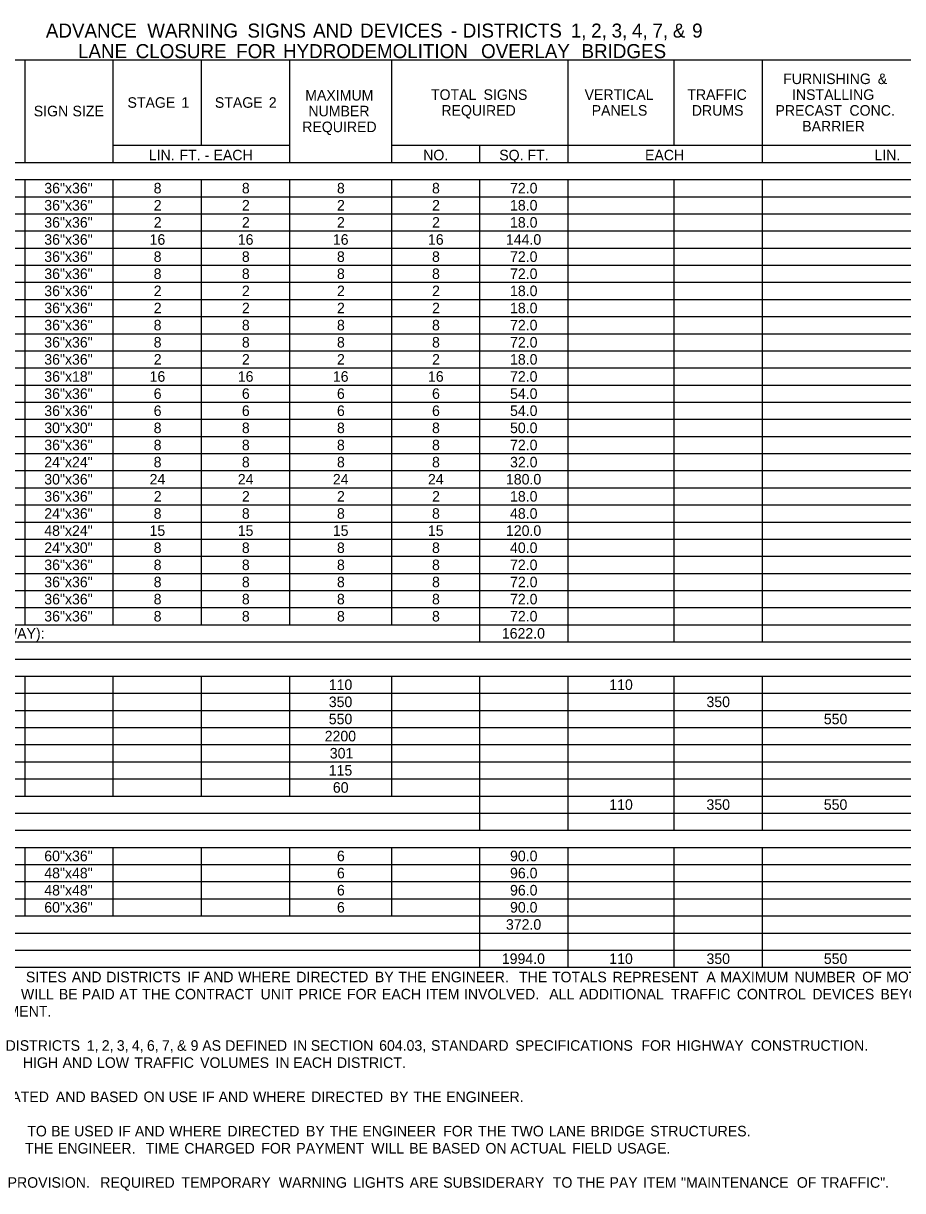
# Model space of a CAD drawing. Extents: x 544255 to 1930787, y -1947044 to 596640.
# Drawn here: x 548600 to 549101, y -1946880 to -1946216 of the extents above; entities that cross this region are included whole.
import ezdxf

# ---------------------------------------------------------------- set-up
doc = ezdxf.new("R2010")
doc.units = 0
doc.layers.add('Default', color=7, linetype='Continuous')

msp = doc.modelspace()

# ---------------------------------------------------------------- linework, layer by layer
at = {"layer": 'Default'}
for p, q in [((548283.35, -1946236.45), (549393.87, -1946236.45)), ((548601.2, -1946294.95), (548601.2, -1946236.45)), ((548651.41, -1946294.95), (548651.41, -1946236.45)), ((548701.62, -1946285.2), (548701.62, -1946236.45)), ((548751.84, -1946294.95), (548751.84, -1946236.45)), ((548809.85, -1946294.95), (548809.85, -1946236.45)), ((548910.27, -1946294.95), (548910.27, -1946236.45)), ((548970.72, -1946285.2), (548970.72, -1946236.45)), ((549020.94, -1946294.95), (549020.94, -1946236.45)), ((548651.41, -1946285.2), (548751.84, -1946285.2)), ((548751.84, -1946294.95), (548751.84, -1946285.2)), ((548809.85, -1946285.2), (549393.87, -1946285.2)), ((548860.06, -1946294.95), (548860.06, -1946285.2)), ((549020.94, -1946294.95), (549020.94, -1946285.2)), ((548283.35, -1946294.95), (549393.87, -1946294.95)), ((548751.84, -1946294.95), (549393.87, -1946294.95)), ((548283.35, -1946304.7), (549393.87, -1946304.7)), ((548601.2, -1946558.2), (548601.2, -1946304.7)), ((548601.2, -1946558.2), (548601.2, -1946304.7)), ((548651.41, -1946558.2), (548651.41, -1946304.7)), ((548651.41, -1946558.2), (548651.41, -1946304.7)), ((548701.62, -1946558.2), (548701.62, -1946304.7)), ((548701.62, -1946558.2), (548701.62, -1946304.7)), ((548751.84, -1946558.2), (548751.84, -1946304.7)), ((548751.84, -1946558.2), (548751.84, -1946304.7)), ((548809.85, -1946558.2), (548809.85, -1946304.7)), ((548860.06, -1946558.2), (548860.06, -1946304.7)), ((548860.06, -1946567.95), (548860.06, -1946304.7)), ((548910.27, -1946548.45), (548910.27, -1946304.7)), ((548910.27, -1946567.95), (548910.27, -1946304.7)), ((548970.72, -1946567.95), (548970.72, -1946304.7)), ((548970.72, -1946567.95), (548970.72, -1946304.7)), ((549020.94, -1946567.95), (549020.94, -1946304.7)), ((549020.94, -1946567.95), (549020.94, -1946304.7)), ((548283.35, -1946314.45), (549393.87, -1946314.45)), ((548283.35, -1946324.2), (549393.87, -1946324.2)), ((548283.35, -1946333.95), (549393.87, -1946333.95)), ((548283.35, -1946343.7), (549393.87, -1946343.7)), ((548283.35, -1946353.45), (549393.87, -1946353.45)), ((548283.35, -1946363.2), (549393.87, -1946363.2)), ((548283.35, -1946372.95), (549393.87, -1946372.95)), ((548283.35, -1946382.7), (549393.87, -1946382.7)), ((548283.35, -1946392.45), (549393.87, -1946392.45)), ((548283.35, -1946402.2), (549393.87, -1946402.2)), ((548283.35, -1946411.95), (549393.87, -1946411.95)), ((548283.35, -1946421.7), (549393.87, -1946421.7)), ((548283.35, -1946431.45), (549393.87, -1946431.45)), ((548283.35, -1946441.2), (549393.87, -1946441.2)), ((548283.35, -1946450.95), (549393.87, -1946450.95)), ((548283.35, -1946460.7), (549393.87, -1946460.7)), ((548283.35, -1946470.45), (549393.87, -1946470.45)), ((548283.35, -1946480.2), (549393.87, -1946480.2)), ((548283.35, -1946489.95), (549393.87, -1946489.95)), ((548283.35, -1946499.7), (549393.87, -1946499.7)), ((548283.35, -1946509.45), (549393.87, -1946509.45)), ((548283.35, -1946519.2), (549393.87, -1946519.2)), ((548283.35, -1946528.95), (549393.87, -1946528.95)), ((548283.35, -1946538.7), (549393.87, -1946538.7)), ((548283.35, -1946548.45), (549393.87, -1946548.45)), ((548283.35, -1946558.2), (549393.87, -1946558.2)), ((548283.35, -1946558.2), (549393.87, -1946558.2)), ((548910.27, -1946567.95), (548910.27, -1946558.2)), ((548283.35, -1946567.95), (549393.87, -1946567.95)), ((548283.35, -1946577.7), (549393.87, -1946577.7)), ((548283.35, -1946577.7), (549393.87, -1946577.7)), ((548283.35, -1946587.45), (549393.87, -1946587.45)), ((548601.2, -1946655.7), (548601.2, -1946587.45)), ((548601.2, -1946655.7), (548601.2, -1946587.45)), ((548651.41, -1946655.7), (548651.41, -1946587.45)), ((548651.41, -1946655.7), (548651.41, -1946587.45)), ((548701.62, -1946655.7), (548701.62, -1946587.45)), ((548701.62, -1946655.7), (548701.62, -1946587.45)), ((548751.84, -1946655.7), (548751.84, -1946587.45)), ((548751.84, -1946655.7), (548751.84, -1946587.45)), ((548809.85, -1946655.7), (548809.85, -1946587.45)), ((548860.06, -1946675.2), (548860.06, -1946587.45)), ((548860.06, -1946675.2), (548860.06, -1946587.45)), ((548910.27, -1946675.2), (548910.27, -1946587.45)), ((548910.27, -1946675.2), (548910.27, -1946587.45)), ((548970.72, -1946675.2), (548970.72, -1946587.45)), ((548970.72, -1946675.2), (548970.72, -1946587.45)), ((549020.94, -1946675.2), (549020.94, -1946587.45)), ((549020.94, -1946675.2), (549020.94, -1946587.45)), ((548283.35, -1946597.2), (549393.87, -1946597.2)), ((548283.35, -1946606.95), (549393.87, -1946606.95)), ((548283.35, -1946616.7), (549393.87, -1946616.7)), ((548601.2, -1946616.7), (548751.84, -1946616.7)), ((548751.84, -1946616.7), (548809.85, -1946616.7)), ((548809.85, -1946616.7), (549020.94, -1946616.7)), ((549020.94, -1946616.7), (549393.87, -1946616.7)), ((548283.35, -1946626.45), (549393.87, -1946626.45)), ((548283.35, -1946636.2), (549393.87, -1946636.2)), ((548283.35, -1946645.95), (549393.87, -1946645.95)), ((548809.85, -1946655.7), (548809.85, -1946645.95)), ((548283.35, -1946655.7), (548809.85, -1946655.7)), ((548283.35, -1946655.7), (549393.87, -1946655.7)), ((548809.85, -1946655.7), (549393.87, -1946655.7)), ((548283.35, -1946665.45), (549393.87, -1946665.45)), ((548283.35, -1946675.2), (549393.87, -1946675.2)), ((548283.35, -1946684.95), (549393.87, -1946684.95)), ((548601.2, -1946723.95), (548601.2, -1946684.95)), ((548651.41, -1946723.95), (548651.41, -1946684.95)), ((548701.62, -1946723.95), (548701.62, -1946684.95)), ((548751.84, -1946723.95), (548751.84, -1946684.95)), ((548809.85, -1946723.95), (548809.85, -1946684.95)), ((548860.06, -1946753.2), (548860.06, -1946684.95)), ((548910.27, -1946753.2), (548910.27, -1946684.95)), ((548910.27, -1946753.2), (548910.27, -1946684.95)), ((548970.72, -1946753.2), (548970.72, -1946684.95)), ((549020.94, -1946753.2), (549020.94, -1946684.95)), ((548283.35, -1946694.7), (549393.87, -1946694.7)), ((548283.35, -1946704.45), (549393.87, -1946704.45)), ((548283.35, -1946714.2), (549393.87, -1946714.2)), ((548283.35, -1946723.95), (549393.87, -1946723.95)), ((548860.06, -1946723.95), (548910.27, -1946723.95)), ((548860.06, -1946753.2), (548860.06, -1946723.95)), ((548910.27, -1946723.95), (549393.87, -1946723.95)), ((548970.72, -1946753.2), (548970.72, -1946723.95)), ((549020.94, -1946753.2), (549020.94, -1946723.95)), ((548283.35, -1946733.7), (549393.87, -1946733.7)), ((548283.35, -1946743.45), (549393.87, -1946743.45)), ((548283.35, -1946753.2), (549393.87, -1946753.2))]:
    msp.add_line(p, q, dxfattribs=at)

# ---------------------------------------------------------------- texts
for s, height, p in [('ADVANCE', 8, (548613, -1946223.88)), (' WARNING', 8, (548667.73, -1946223.88)), (' SIGNS', 8, (548724.79, -1946223.88)), (' AND', 8, (548762.14, -1946223.88)), (' DEVICES', 8, (548788.9, -1946223.88)), (' DISTRICTS', 8, (548847.28, -1946223.88)), (' 1,', 8, (548908.84, -1946223.88)), (' 2,', 8, (548920.45, -1946223.88)), (' 3,', 8, (548932.07, -1946223.88)), (' 4,', 8, (548943.68, -1946223.88)), (' 7,', 8, (548955.3, -1946223.88)), (' &', 8, (548966.92, -1946223.88)), (' 9', 8, (548977.91, -1946223.88)), (' -', 8, (548840.54, -1946223.88)), ('LANE', 8, (548631.29, -1946235.58)), (' CLOSURE', 8, (548661.17, -1946235.58)), (' FOR', 8, (548718.37, -1946235.58)), (' HYDRODEMOLITION', 8, (548745.02, -1946235.58)), (' OVERLAY', 8, (548857.77, -1946235.58)), (' BRIDGES', 8, (548914.93, -1946235.58)), ('FURNISHING', 6, (549032.67, -1946250.33)), (' &', 6, (549084.32, -1946250.33)), ('STAGE', 6, (548659.47, -1946263.83)), (' 1', 6, (548687.94, -1946263.83)), ('STAGE', 6, (548709.21, -1946263.83)), (' 2', 6, (548737.68, -1946263.83)), ('MAXIMUM', 6, (548760.65, -1946259.7)), ('TOTAL', 6, (548832.21, -1946259.33)), (' SIGNS', 6, (548859.9, -1946259.33)), ('VERTICAL', 6, (548919.66, -1946259.33)), ('TRAFFIC', 6, (548978.12, -1946259.33)), ('INSTALLING', 6, (549037.72, -1946259.33)), ('SIGN', 6, (548606.12, -1946268.7)), (' SIZE', 6, (548625.94, -1946268.7)), ('NUMBER', 6, (548762.47, -1946268.7)), ('REQUIRED', 6, (548838.14, -1946268.33)), ('PANELS', 6, (548923.7, -1946268.33)), ('DRUMS', 6, (548980.67, -1946268.33)), ('PRECAST', 6, (549028.29, -1946268.33)), (' CONC.', 6, (549068.18, -1946268.33)), ('REQUIRED', 6, (548758.92, -1946277.7)), ('BARRIER', 6, (549043.54, -1946277.33)), ('LIN.', 6, (548671.59, -1946293.75)), (' FT.', 6, (548686.84, -1946293.75)), (' -', 6, (548701.16, -1946293.75)), (' EACH', 6, (548706.22, -1946293.75)), ('NO.', 6, (548827.79, -1946293.75)), ('SQ.', 6, (548871.07, -1946293.75)), (' FT.', 6, (548884.94, -1946293.75)), ('EACH', 6, (548954.05, -1946293.75)), ('LIN.', 6, (549084.63, -1946293.75)), ('36"x36"', 6, (548612.11, -1946312.58)), ('8', 6, (548674.37, -1946312.58)), ('8', 6, (548724.59, -1946312.58)), ('8', 6, (548778.7, -1946312.58)), ('8', 6, (548832.81, -1946312.58)), ('72.0', 6, (548877.22, -1946312.58)), ('36"x36"', 6, (548612.11, -1946322.33)), ('2', 6, (548674.41, -1946322.33)), ('2', 6, (548724.62, -1946322.33)), ('2', 6, (548778.73, -1946322.33)), ('2', 6, (548832.85, -1946322.33)), ('18.0', 6, (548877.22, -1946322.33)), ('36"x36"', 6, (548612.11, -1946332.08)), ('2', 6, (548674.41, -1946332.08)), ('2', 6, (548724.62, -1946332.08)), ('2', 6, (548778.73, -1946332.08)), ('2', 6, (548832.85, -1946332.08)), ('18.0', 6, (548877.22, -1946332.08)), ('36"x36"', 6, (548612.11, -1946341.83)), ('16', 6, (548672.05, -1946341.83)), ('16', 6, (548722.26, -1946341.83)), ('16', 6, (548776.37, -1946341.83)), ('16', 6, (548830.49, -1946341.83)), ('144.0', 6, (548874.89, -1946341.83)), ('36"x36"', 6, (548612.11, -1946351.58)), ('8', 6, (548674.37, -1946351.58)), ('8', 6, (548724.59, -1946351.58)), ('8', 6, (548778.7, -1946351.58)), ('8', 6, (548832.81, -1946351.58)), ('72.0', 6, (548877.22, -1946351.58)), ('36"x36"', 6, (548612.11, -1946361.33)), ('8', 6, (548674.37, -1946361.33)), ('8', 6, (548724.59, -1946361.33)), ('8', 6, (548778.7, -1946361.33)), ('8', 6, (548832.81, -1946361.33)), ('72.0', 6, (548877.22, -1946361.33)), ('36"x36"', 6, (548612.11, -1946371.08)), ('2', 6, (548674.41, -1946371.08)), ('2', 6, (548724.62, -1946371.08)), ('2', 6, (548778.73, -1946371.08)), ('2', 6, (548832.85, -1946371.08)), ('18.0', 6, (548877.22, -1946371.08)), ('36"x36"', 6, (548612.11, -1946380.83)), ('2', 6, (548674.41, -1946380.83)), ('2', 6, (548724.62, -1946380.83)), ('2', 6, (548778.73, -1946380.83)), ('2', 6, (548832.85, -1946380.83)), ('18.0', 6, (548877.22, -1946380.83)), ('36"x36"', 6, (548612.11, -1946390.58)), ('8', 6, (548674.37, -1946390.58)), ('8', 6, (548724.59, -1946390.58)), ('8', 6, (548778.7, -1946390.58)), ('8', 6, (548832.81, -1946390.58)), ('72.0', 6, (548877.22, -1946390.58)), ('36"x36"', 6, (548612.11, -1946400.33)), ('8', 6, (548674.37, -1946400.33)), ('8', 6, (548724.59, -1946400.33)), ('8', 6, (548778.7, -1946400.33)), ('8', 6, (548832.81, -1946400.33)), ('72.0', 6, (548877.22, -1946400.33)), ('36"x36"', 6, (548612.11, -1946410.08)), ('2', 6, (548674.41, -1946410.08)), ('2', 6, (548724.62, -1946410.08)), ('2', 6, (548778.73, -1946410.08)), ('2', 6, (548832.85, -1946410.08)), ('18.0', 6, (548877.22, -1946410.08)), ('36"x18"', 6, (548612.11, -1946419.83)), ('16', 6, (548672.05, -1946419.83)), ('16', 6, (548722.26, -1946419.83)), ('16', 6, (548776.37, -1946419.83)), ('16', 6, (548830.49, -1946419.83)), ('72.0', 6, (548877.22, -1946419.83)), ('36"x36"', 6, (548612.11, -1946429.58)), ('6', 6, (548674.38, -1946429.58)), ('6', 6, (548724.59, -1946429.58)), ('6', 6, (548778.7, -1946429.58)), ('6', 6, (548832.82, -1946429.58)), ('54.0', 6, (548877.22, -1946429.58)), ('36"x36"', 6, (548612.11, -1946439.33)), ('6', 6, (548674.38, -1946439.33)), ('6', 6, (548724.59, -1946439.33)), ('6', 6, (548778.7, -1946439.33)), ('6', 6, (548832.82, -1946439.33)), ('54.0', 6, (548877.22, -1946439.33)), ('30"x30"', 6, (548612.11, -1946449.08)), ('8', 6, (548674.37, -1946449.08)), ('8', 6, (548724.59, -1946449.08)), ('8', 6, (548778.7, -1946449.08)), ('8', 6, (548832.81, -1946449.08)), ('50.0', 6, (548877.22, -1946449.08)), ('36"x36"', 6, (548612.11, -1946458.83)), ('8', 6, (548674.37, -1946458.83)), ('8', 6, (548724.59, -1946458.83)), ('8', 6, (548778.7, -1946458.83)), ('8', 6, (548832.81, -1946458.83)), ('72.0', 6, (548877.22, -1946458.83)), ('24"x24"', 6, (548612.11, -1946468.58)), ('8', 6, (548674.37, -1946468.58)), ('8', 6, (548724.59, -1946468.58)), ('8', 6, (548778.7, -1946468.58)), ('8', 6, (548832.81, -1946468.58)), ('32.0', 6, (548877.22, -1946468.58)), ('30"x36"', 6, (548612.11, -1946478.33)), ('24', 6, (548672.06, -1946478.33)), ('24', 6, (548722.27, -1946478.33)), ('24', 6, (548776.39, -1946478.33)), ('24', 6, (548830.5, -1946478.33)), ('180.0', 6, (548874.89, -1946478.33)), ('36"x36"', 6, (548612.11, -1946488.08)), ('2', 6, (548674.41, -1946488.08)), ('2', 6, (548724.62, -1946488.08)), ('2', 6, (548778.73, -1946488.08)), ('2', 6, (548832.85, -1946488.08)), ('18.0', 6, (548877.22, -1946488.08)), ('24"x36"', 6, (548612.11, -1946497.83)), ('8', 6, (548674.37, -1946497.83)), ('8', 6, (548724.59, -1946497.83)), ('8', 6, (548778.7, -1946497.83)), ('8', 6, (548832.81, -1946497.83)), ('48.0', 6, (548877.22, -1946497.83)), ('48"x24"', 6, (548612.11, -1946507.58)), ('15', 6, (548672.02, -1946507.58)), ('15', 6, (548722.24, -1946507.58)), ('15', 6, (548776.35, -1946507.58)), ('15', 6, (548830.46, -1946507.58)), ('120.0', 6, (548874.89, -1946507.58)), ('24"x30"', 6, (548612.11, -1946517.33)), ('8', 6, (548674.37, -1946517.33)), ('8', 6, (548724.59, -1946517.33)), ('8', 6, (548778.7, -1946517.33)), ('8', 6, (548832.81, -1946517.33)), ('40.0', 6, (548877.22, -1946517.33)), ('36"x36"', 6, (548612.11, -1946527.08)), ('8', 6, (548674.37, -1946527.08)), ('8', 6, (548724.59, -1946527.08)), ('8', 6, (548778.7, -1946527.08)), ('8', 6, (548832.81, -1946527.08)), ('72.0', 6, (548877.22, -1946527.08)), ('36"x36"', 6, (548612.11, -1946536.83)), ('8', 6, (548674.37, -1946536.83)), ('8', 6, (548724.59, -1946536.83)), ('8', 6, (548778.7, -1946536.83)), ('8', 6, (548832.81, -1946536.83)), ('72.0', 6, (548877.22, -1946536.83)), ('36"x36"', 6, (548612.11, -1946546.58)), ('8', 6, (548674.37, -1946546.58)), ('8', 6, (548724.59, -1946546.58)), ('8', 6, (548778.7, -1946546.58)), ('8', 6, (548832.81, -1946546.58)), ('72.0', 6, (548877.22, -1946546.58)), ('36"x36"', 6, (548612.11, -1946556.33)), ('8', 6, (548674.37, -1946556.33)), ('8', 6, (548724.59, -1946556.33)), ('8', 6, (548778.7, -1946556.33)), ('8', 6, (548832.81, -1946556.33)), ('72.0', 6, (548877.22, -1946556.33)), (' HIGHWAY):', 6, (548566.8, -1946566.08)), ('1622.0', 6, (548872.56, -1946566.08)), ('110', 6, (548774.05, -1946595.33)), ('110', 6, (548933.71, -1946595.33)), ('350', 6, (548774.05, -1946605.08)), ('350', 6, (548989.04, -1946605.08)), ('550', 6, (548774.05, -1946614.83)), ('550', 6, (549055.83, -1946614.83)), ('2200', 6, (548771.72, -1946624.58)), ('301', 6, (548774.62, -1946634.33)), ('115', 6, (548774.02, -1946644.08)), ('60', 6, (548776.38, -1946653.83)), ('110', 6, (548933.71, -1946663.58)), ('350', 6, (548989.05, -1946663.58)), ('550', 6, (549055.83, -1946663.58)), ('60"x36"', 6, (548612.11, -1946692.83)), ('6', 6, (548778.7, -1946692.83)), ('90.0', 6, (548877.22, -1946692.83)), ('48"x48"', 6, (548612.11, -1946702.58)), ('6', 6, (548778.7, -1946702.58)), ('96.0', 6, (548877.22, -1946702.58)), ('48"x48"', 6, (548612.11, -1946712.33)), ('6', 6, (548778.7, -1946712.33)), ('96.0', 6, (548877.22, -1946712.33)), ('60"x36"', 6, (548612.11, -1946722.08)), ('6', 6, (548778.7, -1946722.08)), ('90.0', 6, (548877.22, -1946722.08)), ('372.0', 6, (548874.89, -1946731.83)), ('1994.0', 6, (548872.56, -1946751.33)), ('110', 6, (548933.71, -1946751.33)), ('350', 6, (548989.05, -1946751.33)), ('550', 6, (549055.83, -1946751.33)), (' SITES', 6, (548599.42, -1946761.75)), (' AND', 6, (548625.54, -1946761.75)), (' DISTRICTS', 6, (548645.12, -1946761.75)), (' IF', 6, (548691.26, -1946761.75)), (' AND', 6, (548700.65, -1946761.75)), (' WHERE', 6, (548720.23, -1946761.75)), (' DIRECTED', 6, (548753.32, -1946761.75)), (' BY', 6, (548798.06, -1946761.75)), (' THE', 6, (548811.51, -1946761.75)), (' ENGINEER.', 6, (548830.15, -1946761.75)), ('  THE', 6, (548877.87, -1946761.75)), (' TOTALS', 6, (548898.85, -1946761.75)), (' REPRESENT', 6, (548933.35, -1946761.75)), (' A', 6, (548986.76, -1946761.75)), (' MAXIMUM', 6, (548994.69, -1946761.75)), (' NUMBER', 6, (549036.91, -1946761.75)), (' OF', 6, (549075.46, -1946761.75)), (' MOT', 6, (549089.04, -1946761.75)), (' WILL', 6, (548596.59, -1946771.5)), (' BE', 6, (548618.18, -1946771.5)), (' PAID', 6, (548631.25, -1946771.5)), (' AT', 6, (548652.7, -1946771.5)), (' THE', 6, (548665.57, -1946771.5)), (' CONTRACT', 6, (548684.22, -1946771.5)), (' UNIT', 6, (548732.96, -1946771.5)), (' PRICE', 6, (548754.67, -1946771.5)), (' FOR', 6, (548782.18, -1946771.5)), (' EACH', 6, (548802.09, -1946771.5)), (' ITEM', 6, (548827.04, -1946771.5)), (' INVOLVED.', 6, (548848.76, -1946771.5)), ('  ALL', 6, (548895.08, -1946771.5)), (' ADDITIONAL', 6, (548914.35, -1946771.5)), (' TRAFFIC', 6, (548966.69, -1946771.5)), (' CONTROL', 6, (549004.08, -1946771.5)), (' DEVICES', 6, (549047.1, -1946771.5)), (' BEYOND', 6, (549085.8, -1946771.5)), (' DEPARTMENT.', 6, (548556.42, -1946781.25)), (' DISTRICTS', 6, (548587.89, -1946800.75)), (' 1,', 6, (548634.03, -1946800.75)), (' 2,', 6, (548642.6, -1946800.75)), (' 3,', 6, (548651.17, -1946800.75)), (' 4,', 6, (548659.74, -1946800.75)), (' 6,', 6, (548668.31, -1946800.75)), (' 7,', 6, (548676.88, -1946800.75)), (' &', 6, (548685.45, -1946800.75)), (' 9', 6, (548693.17, -1946800.75)), (' AS', 6, (548699.79, -1946800.75)), (' DEFINED', 6, (548712.87, -1946800.75)), (' IN', 6, (548751.55, -1946800.75)), (' SECTION', 6, (548761.57, -1946800.75)), (' 604.03,', 6, (548800.48, -1946800.75)), (' STANDARD', 6, (548830.02, -1946800.75)), (' SPECIFICATIONS', 6, (548878.02, -1946800.75)), (' FOR', 6, (548949.78, -1946800.75)), (' HIGHWAY', 6, (548969.7, -1946800.75)), (' CONSTRUCTION.', 6, (549012.02, -1946800.75)), (' HIGH', 6, (548597.67, -1946810.5)), (' AND', 6, (548620.28, -1946810.5)), (' LOW', 6, (548639.87, -1946810.5)), (' TRAFFIC', 6, (548661.19, -1946810.5)), (' VOLUMES', 6, (548698.58, -1946810.5)), (' IN', 6, (548741.47, -1946810.5)), (' EACH', 6, (548751.49, -1946810.5)), (' DISTRICT.', 6, (548776.44, -1946810.5)), (' ESTIMATED', 6, (548566.61, -1946830)), (' AND', 6, (548616.47, -1946830)), (' BASED', 6, (548636.05, -1946830)), (' ON', 6, (548666.36, -1946830)), (' USE', 6, (548680.58, -1946830)), (' IF', 6, (548699.7, -1946830)), (' AND', 6, (548709.09, -1946830)), (' WHERE', 6, (548728.67, -1946830)), (' DIRECTED', 6, (548761.76, -1946830)), (' BY', 6, (548806.49, -1946830)), (' THE', 6, (548819.94, -1946830)), (' ENGINEER.', 6, (548838.59, -1946830)), (' TO', 6, (548600.2, -1946849.5)), (' BE', 6, (548613.79, -1946849.5)), (' USED', 6, (548626.86, -1946849.5)), (' IF', 6, (548652.03, -1946849.5)), (' AND', 6, (548661.43, -1946849.5)), (' WHERE', 6, (548681.01, -1946849.5)), (' DIRECTED', 6, (548714.1, -1946849.5)), (' BY', 6, (548758.83, -1946849.5)), (' THE', 6, (548772.28, -1946849.5)), (' ENGINEER', 6, (548790.93, -1946849.5)), (' FOR', 6, (548836.94, -1946849.5)), (' THE', 6, (548856.85, -1946849.5)), (' TWO', 6, (548875.5, -1946849.5)), (' LANE', 6, (548897.01, -1946849.5)), (' BRIDGE', 6, (548920.79, -1946849.5)), (' STRUCTURES.', 6, (548954.81, -1946849.5)), (' THE', 6, (548599, -1946859.25)), (' ENGINEER.', 6, (548617.65, -1946859.25)), ('  TIME', 6, (548665.37, -1946859.25)), (' CHARGED', 6, (548689.6, -1946859.25)), (' FOR', 6, (548733.4, -1946859.25)), (' PAYMENT', 6, (548753.32, -1946859.25)), (' WILL', 6, (548796.01, -1946859.25)), (' BE', 6, (548817.6, -1946859.25)), (' BASED', 6, (548830.66, -1946859.25)), (' ON', 6, (548860.97, -1946859.25)), (' ACTUAL', 6, (548875.19, -1946859.25)), (' FIELD', 6, (548910.3, -1946859.25)), (' USAGE.', 6, (548935.93, -1946859.25)), (' PROVISION.', 6, (548589.01, -1946878.75)), ('  REQUIRED', 6, (548639.52, -1946878.75)), (' TEMPORARY', 6, (548687.98, -1946878.75)), (' WARNING', 6, (548743.36, -1946878.75)), (' LIGHTS', 6, (548785.68, -1946878.75)), (' ARE', 6, (548817.84, -1946878.75)), (' SUBSIDERARY', 6, (548836.96, -1946878.75)), (' TO', 6, (548899.33, -1946878.75)), (' THE', 6, (548912.93, -1946878.75)), (' PAY', 6, (548931.58, -1946878.75)), (' ITEM', 6, (548950.62, -1946878.75)), (' "MAINTENANCE', 6, (548972.34, -1946878.75)), (' OF', 6, (549038.23, -1946878.75)), (' TRAFFIC".', 6, (549051.81, -1946878.75))]:
    msp.add_text(s, height=height, dxfattribs=at).set_placement(p)

doc.saveas('drawing.dxf')
